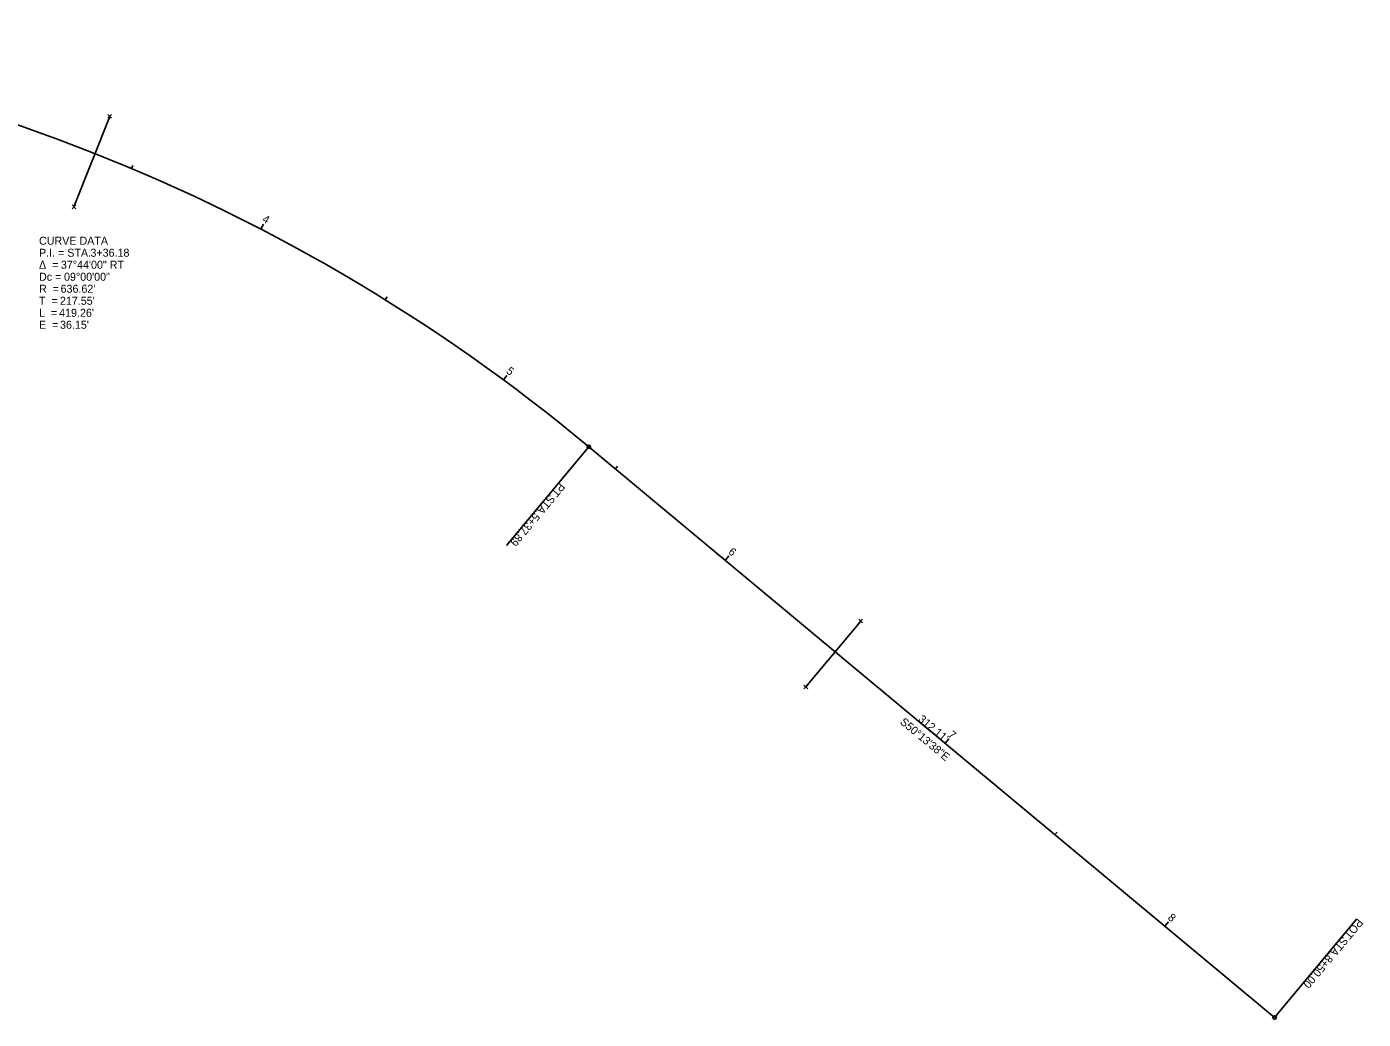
# Model space of a CAD drawing. Extents: x 1609531 to 1610891, y 471231 to 473177.
# Drawn here: x 1610423.2 to 1610890.7, y 471886.1 to 472233.3 of the extents above; entities that cross this region are included whole.
import ezdxf

# ---------------------------------------------------------------- set-up
doc = ezdxf.new("R2010")
doc.units = 0
for name, color, linetype in [('BR_X_SV_Shot_Marker', 7, 'Continuous'), ('Default', 7, 'Continuous'), ('PV_X_COP', 7, 'Continuous'), ('PV_X_EOP', 7, 'Continuous'), ('PV_X_Shoulder_Aggregate', 7, 'Continuous'), ('RD_X_Cells', 7, 'Continuous'), ('SV_X_Control_Cells_Found', 7, 'Continuous'), ('UT_X_Misc_Cells', 7, 'Continuous'), ('UT_X_Telecom_Cells', 7, 'Continuous')]:
    doc.layers.add(name, color=color, linetype=linetype)

msp = doc.modelspace()

# ---------------------------------------------------------------- linework, layer by layer
at = {"layer": 'Default'}
msp.add_line((1610619.8, 472086.35), (1610859.69, 471886.68), dxfattribs=at)
msp.add_arc((1610212.53, 471597.05), 636.62, 50.22722, 87.96056, dxfattribs=at)
at = {"layer": 'PV_X_COP'}
for p, q in [((1610451.57, 472201.23), (1610452.9, 472202.57)), ((1610451.57, 472202.57), (1610452.9, 472201.23)), ((1610439.04, 472169.62), (1610440.38, 472170.96)), ((1610439.04, 472170.96), (1610440.38, 472169.62)), ((1610714.26, 472024.72), (1610715.59, 472026.05)), ((1610714.26, 472026.05), (1610715.59, 472024.72)), ((1610695.07, 472001.66), (1610696.4, 472002.99)), ((1610695.07, 472002.99), (1610696.4, 472001.66))]:
    msp.add_line(p, q, dxfattribs=at)
at = {"layer": 'PV_X_Shoulder_Aggregate'}
for p, q in [((1610459.87, 472183.65), (1610460.34, 472184.76)), ((1610505.13, 472162.44), (1610506.05, 472164.22)), ((1610548.59, 472137.74), (1610549.23, 472138.76)), ((1610589.98, 472109.71), (1610591.16, 472111.32)), ((1610629.11, 472078.6), (1610629.88, 472079.52)), ((1610667.54, 472046.61), (1610668.82, 472048.15)), ((1610705.97, 472014.62), (1610706.74, 472015.55)), ((1610744.4, 471982.64), (1610745.68, 471984.17)), ((1610782.83, 471950.65), (1610783.6, 471951.57)), ((1610821.26, 471918.66), (1610822.54, 471920.2))]:
    msp.add_line(p, q, dxfattribs=at)
at = {"layer": 'RD_X_Cells'}
for p, q in [((1610452.24, 472201.9), (1610439.71, 472170.29)), ((1610714.93, 472025.38), (1610695.73, 472002.33))]:
    msp.add_line(p, q, dxfattribs=at)
at = {"layer": 'SV_X_Control_Cells_Found'}
for p, q in [((1610619.8, 472086.35), (1610591.02, 472051.76)), ((1610859.69, 471886.68), (1610888.48, 471921.26))]:
    msp.add_line(p, q, dxfattribs=at)
for centre in [(1610619.8, 472086.35), (1610859.69, 471886.68)]:
    msp.add_circle(centre, 0.6, dxfattribs=at)
at = {"layer": 'UT_X_Misc_Cells'}
msp.add_line((1610619.8, 472086.35), (1610859.69, 471886.68), dxfattribs=at)
msp.add_arc((1610212.53, 471597.05), 636.62, 50.22722, 87.96056, dxfattribs=at)

# ---------------------------------------------------------------- texts
at = {"layer": 'BR_X_SV_Shot_Marker'}
for s, p in [('CURVE DATA', (1610427.49, 472157.01)), ('P.I. = STA. ', (1610427.49, 472152.81)), ('3+36.18', (1610445.48, 472152.81)), ('Δ  = ', (1610427.49, 472148.61)), ('37°44\'00" RT', (1610435.14, 472148.61)), ('Dc = ', (1610427.49, 472144.41)), ('09°00\'00"', (1610436.24, 472144.41)), ('R  = ', (1610427.49, 472140.21)), ("636.62'", (1610435.03, 472140.21)), ('T  = ', (1610427.49, 472136.01)), ("217.55'", (1610434.81, 472136.01)), ('L  = ', (1610427.49, 472131.81)), ('E  = ', (1610427.49, 472127.61)), ("419.26'", (1610434.53, 472131.81)), ("36.15'", (1610434.84, 472127.61))]:
    msp.add_text(s, height=2.8, dxfattribs=at).set_placement(p)
at = {"layer": 'PV_X_EOP'}
msp.add_text("312.11'", height=2.8, rotation=320.2272, dxfattribs=at).set_placement((1610734.82, 471990.66))
at = {"layer": 'PV_X_Shoulder_Aggregate'}
for s, rotation, p in [('4', 332.6373, (1610505.35, 472165.14)), ('5', 323.6373, (1610590.68, 472112.3)), ('6', 320.2272, (1610668.36, 472049.19)), ('7', 320.2272, (1610745.22, 471985.2)), ('8', 320.2272, (1610822.08, 471921.23))]:
    msp.add_text(s, height=2.8, rotation=rotation, dxfattribs=at).set_placement(p)
at = {"layer": 'SV_X_Control_Cells_Found'}
for s, p in [(' STA. ', (1610606.77, 472070.63)), ('PT', (1610609.55, 472073.98)), ('5+37.89', (1610600.81, 472063.47)), ('POT', (1610888.74, 471921.52)), (' STA. ', (1610884.18, 471916.04)), ('8+50.00', (1610878.21, 471908.88))]:
    msp.add_text(s, height=2.8, rotation=230.2272, dxfattribs=at).set_placement(p)
at = {"layer": 'UT_X_Telecom_Cells'}
msp.add_text('S50°13\'38"E', height=2.8, rotation=320.2272, dxfattribs=at).set_placement((1610728.44, 471989.67))

doc.saveas('drawing.dxf')
